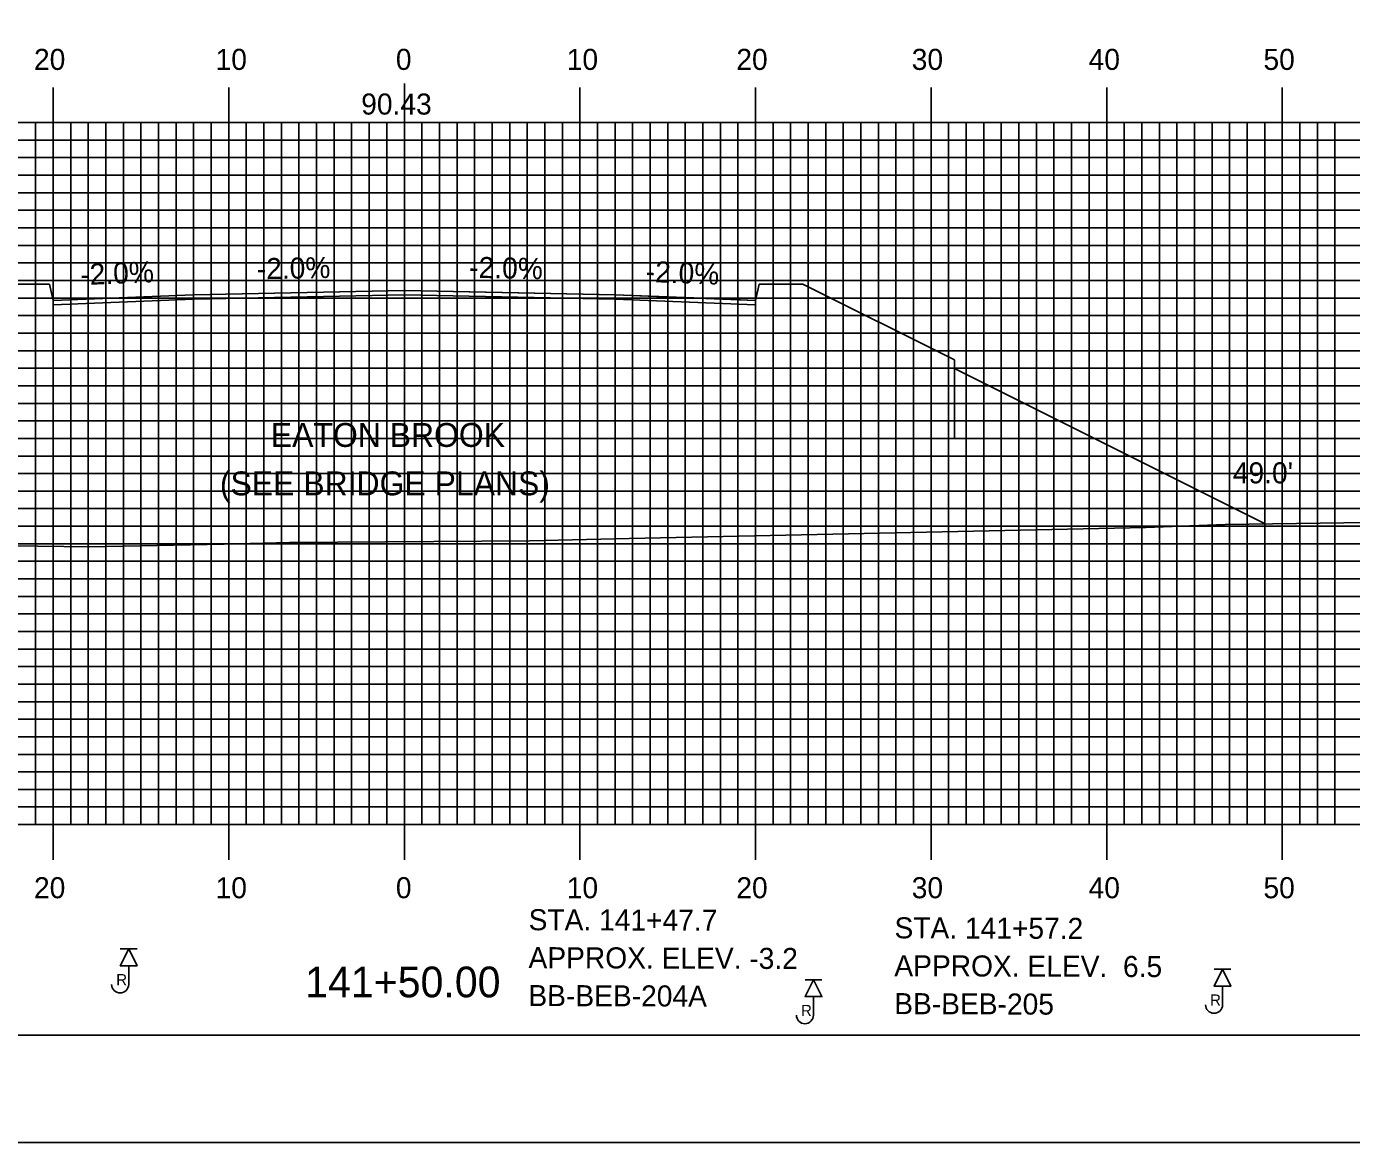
# Model space of a CAD drawing. Extents: x 1776744 to 1777088, y 442591 to 442811.
# Drawn here: x 1776888.7 to 1776964.2, y 442590.5 to 442654.1 of the extents above; entities that cross this region are included whole.
import ezdxf

# ---------------------------------------------------------------- set-up
doc = ezdxf.new("R2010")
doc.units = 0
for name, color, linetype in [('ANNOTATION', 7, 'Continuous'), ('BORDER', 7, 'Continuous'), ('BORING - REFUSAL', 7, 'Continuous'), ('D_Roadway_Centerline', 7, 'Continuous'), ('D_Roadway_Centerline_Text', 7, 'Continuous'), ('D_Roadway_Edge_Shoulder', 7, 'Continuous'), ('D_Roadway_Edge_TW', 7, 'Continuous'), ('D_Roadway_SlopeLines', 7, 'Continuous'), ('D_Text_Standard', 7, 'Continuous'), ('H_V ANNOTATION', 7, 'Continuous'), ('MAJOR', 7, 'Continuous'), ('MINOR', 7, 'Continuous'), ('PLOT BOUNDARY', 7, 'Continuous'), ('S_Roadway_Centerline', 7, 'Continuous')]:
    doc.layers.add(name, color=color, linetype=linetype)

msp = doc.modelspace()

# ---------------------------------------------------------------- linework, layer by layer
at = {"layer": 'BORDER'}
msp.add_lwpolyline([(1776760.651, 442596.665), (1777080.651, 442596.665), (1777080.651, 442806.665), (1776760.651, 442806.665)], close=True, dxfattribs=at)
at = {"layer": 'BORING - REFUSAL'}
for p, q in [((1776895.03, 442601.578), (1776894.071, 442601.578)), ((1776894.551, 442600.618), (1776894.551, 442599.559)), ((1776957.33, 442600.417), (1776956.371, 442600.417)), ((1776934.03, 442599.822), (1776933.071, 442599.822)), ((1776933.551, 442598.862), (1776933.551, 442597.803)), ((1776956.851, 442599.457), (1776956.851, 442598.398))]:
    msp.add_line(p, q, dxfattribs=at)
for points in [[(1776894.551, 442601.578), (1776895.03, 442600.618), (1776894.071, 442600.618)], [(1776956.851, 442600.417), (1776957.33, 442599.457), (1776956.371, 442599.457)], [(1776933.551, 442599.822), (1776934.03, 442598.862), (1776933.071, 442598.862)]]:
    msp.add_lwpolyline(points, close=True, dxfattribs=at)
for centre in [(1776894.066, 442599.559), (1776956.366, 442598.398), (1776933.066, 442597.803)]:
    msp.add_arc(centre, 0.485, 180, 0, dxfattribs=at)
at = {"layer": 'D_Roadway_Centerline'}
msp.add_lwpolyline([(1776890.25, 442638.535), (1776890.253, 442638.535), (1776898.251, 442638.855), (1776898.255, 442638.855), (1776910.251, 442639.095), (1776916.772, 442638.965), (1776922.251, 442638.855), (1776922.256, 442638.855), (1776927.228, 442638.656), (1776930.245, 442638.535), (1776930.25, 442638.535)], dxfattribs=at)
at = {"layer": 'D_Roadway_Edge_Shoulder'}
for points in [[(1776898.251, 442638.855), (1776890.25, 442638.535), (1776890.25, 442638.285), (1776898.251, 442638.605)], [(1776922.251, 442638.855), (1776930.25, 442638.535), (1776930.25, 442638.285), (1776922.251, 442638.605)]]:
    msp.add_lwpolyline(points, close=True, dxfattribs=at)
at = {"layer": 'D_Roadway_Edge_TW'}
msp.add_lwpolyline([(1776898.251, 442638.605), (1776898.251, 442638.855), (1776910.251, 442639.095), (1776922.251, 442638.855), (1776922.251, 442638.605), (1776910.251, 442638.845)], close=True, dxfattribs=at)
at = {"layer": 'D_Roadway_SlopeLines'}
for p, q in [((1776890.047, 442639.465), (1776887.547, 442639.465)), ((1776890.247, 442638.535), (1776890.047, 442639.465)), ((1776930.254, 442638.535), (1776930.454, 442639.465)), ((1776930.454, 442639.465), (1776932.954, 442639.465)), ((1776932.954, 442639.465), (1776941.58, 442635.152)), ((1776941.58, 442635.152), (1776941.58, 442630.64)), ((1776941.58, 442634.652), (1776959.283, 442625.801))]:
    msp.add_line(p, q, dxfattribs=at)
at = {"layer": 'MAJOR'}
for p, q in [((1776890.251, 442650.669), (1776890.251, 442648.665)), ((1776900.251, 442650.669), (1776900.251, 442648.665)), ((1776910.251, 442606.661), (1776910.251, 442650.899)), ((1776910.251, 442650.669), (1776910.251, 442648.665)), ((1776920.251, 442650.669), (1776920.251, 442648.665)), ((1776930.251, 442650.669), (1776930.251, 442648.665)), ((1776940.251, 442650.669), (1776940.251, 442648.665)), ((1776950.251, 442650.669), (1776950.251, 442648.665)), ((1776960.251, 442650.669), (1776960.251, 442648.665)), ((1776770.251, 442648.665), (1777050.251, 442648.665)), ((1776770.251, 442648.665), (1777050.251, 442648.665)), ((1776890.251, 442608.665), (1776890.251, 442648.665)), ((1776900.251, 442608.665), (1776900.251, 442648.665)), ((1776910.251, 442608.665), (1776910.251, 442648.665)), ((1776920.251, 442608.665), (1776920.251, 442648.665)), ((1776930.251, 442608.665), (1776930.251, 442648.665)), ((1776940.251, 442608.665), (1776940.251, 442648.665)), ((1776950.251, 442608.665), (1776950.251, 442648.665)), ((1776960.251, 442608.665), (1776960.251, 442648.665)), ((1776770.251, 442643.665), (1777050.251, 442643.665)), ((1776770.251, 442638.665), (1777050.251, 442638.665)), ((1776770.251, 442633.665), (1777050.251, 442633.665)), ((1776770.251, 442628.665), (1777050.251, 442628.665)), ((1776770.251, 442623.665), (1777050.251, 442623.665)), ((1776770.251, 442618.665), (1777050.251, 442618.665)), ((1776770.251, 442613.665), (1777050.251, 442613.665)), ((1776770.251, 442608.665), (1777050.251, 442608.665)), ((1776770.251, 442608.665), (1777050.251, 442608.665)), ((1776890.251, 442606.661), (1776890.251, 442608.665)), ((1776890.251, 442606.661), (1776890.251, 442608.665)), ((1776900.251, 442606.661), (1776900.251, 442608.665)), ((1776900.251, 442606.661), (1776900.251, 442608.665)), ((1776910.251, 442606.661), (1776910.251, 442608.665)), ((1776920.251, 442606.661), (1776920.251, 442608.665)), ((1776920.251, 442606.661), (1776920.251, 442608.665)), ((1776930.251, 442606.661), (1776930.251, 442608.665)), ((1776930.251, 442606.661), (1776930.251, 442608.665)), ((1776940.251, 442606.661), (1776940.251, 442608.665)), ((1776950.251, 442606.661), (1776950.251, 442608.665)), ((1776960.251, 442606.661), (1776960.251, 442608.665))]:
    msp.add_line(p, q, dxfattribs=at)
at = {"layer": 'MINOR'}
for p, q in [((1776889.251, 442608.665), (1776889.251, 442648.665)), ((1776891.251, 442608.665), (1776891.251, 442648.665)), ((1776892.251, 442608.665), (1776892.251, 442648.665)), ((1776893.251, 442608.665), (1776893.251, 442648.665)), ((1776894.251, 442608.665), (1776894.251, 442648.665)), ((1776895.251, 442608.665), (1776895.251, 442648.665)), ((1776896.251, 442608.665), (1776896.251, 442648.665)), ((1776897.251, 442608.665), (1776897.251, 442648.665)), ((1776898.251, 442608.665), (1776898.251, 442648.665)), ((1776899.251, 442608.665), (1776899.251, 442648.665)), ((1776901.251, 442608.665), (1776901.251, 442648.665)), ((1776902.251, 442608.665), (1776902.251, 442648.665)), ((1776903.251, 442608.665), (1776903.251, 442648.665)), ((1776904.251, 442608.665), (1776904.251, 442648.665)), ((1776905.251, 442608.665), (1776905.251, 442648.665)), ((1776906.251, 442608.665), (1776906.251, 442648.665)), ((1776907.251, 442608.665), (1776907.251, 442648.665)), ((1776908.251, 442608.665), (1776908.251, 442648.665)), ((1776909.251, 442608.665), (1776909.251, 442648.665)), ((1776911.251, 442608.665), (1776911.251, 442648.665)), ((1776912.251, 442608.665), (1776912.251, 442648.665)), ((1776913.251, 442608.665), (1776913.251, 442648.665)), ((1776914.251, 442608.665), (1776914.251, 442648.665)), ((1776915.251, 442608.665), (1776915.251, 442648.665)), ((1776916.251, 442608.665), (1776916.251, 442648.665)), ((1776917.251, 442608.665), (1776917.251, 442648.665)), ((1776918.251, 442608.665), (1776918.251, 442648.665)), ((1776919.251, 442608.665), (1776919.251, 442648.665)), ((1776921.251, 442608.665), (1776921.251, 442648.665)), ((1776922.251, 442608.665), (1776922.251, 442648.665)), ((1776923.251, 442608.665), (1776923.251, 442648.665)), ((1776924.251, 442608.665), (1776924.251, 442648.665)), ((1776925.251, 442608.665), (1776925.251, 442648.665)), ((1776926.251, 442608.665), (1776926.251, 442648.665)), ((1776927.251, 442608.665), (1776927.251, 442648.665)), ((1776928.251, 442608.665), (1776928.251, 442648.665)), ((1776929.251, 442608.665), (1776929.251, 442648.665)), ((1776931.251, 442608.665), (1776931.251, 442648.665)), ((1776932.251, 442608.665), (1776932.251, 442648.665)), ((1776933.251, 442608.665), (1776933.251, 442648.665)), ((1776934.251, 442608.665), (1776934.251, 442648.665)), ((1776935.251, 442608.665), (1776935.251, 442648.665)), ((1776936.251, 442608.665), (1776936.251, 442648.665)), ((1776937.251, 442608.665), (1776937.251, 442648.665)), ((1776938.251, 442608.665), (1776938.251, 442648.665)), ((1776939.251, 442608.665), (1776939.251, 442648.665)), ((1776941.251, 442608.665), (1776941.251, 442648.665)), ((1776942.251, 442608.665), (1776942.251, 442648.665)), ((1776943.251, 442608.665), (1776943.251, 442648.665)), ((1776944.251, 442608.665), (1776944.251, 442648.665)), ((1776945.251, 442608.665), (1776945.251, 442648.665)), ((1776946.251, 442608.665), (1776946.251, 442648.665)), ((1776947.251, 442608.665), (1776947.251, 442648.665)), ((1776948.251, 442608.665), (1776948.251, 442648.665)), ((1776949.251, 442608.665), (1776949.251, 442648.665)), ((1776951.251, 442608.665), (1776951.251, 442648.665)), ((1776952.251, 442608.665), (1776952.251, 442648.665)), ((1776953.251, 442608.665), (1776953.251, 442648.665)), ((1776954.251, 442608.665), (1776954.251, 442648.665)), ((1776955.251, 442608.665), (1776955.251, 442648.665)), ((1776956.251, 442608.665), (1776956.251, 442648.665)), ((1776957.251, 442608.665), (1776957.251, 442648.665)), ((1776958.251, 442608.665), (1776958.251, 442648.665)), ((1776959.251, 442608.665), (1776959.251, 442648.665)), ((1776961.251, 442608.665), (1776961.251, 442648.665)), ((1776962.251, 442608.665), (1776962.251, 442648.665)), ((1776963.251, 442608.665), (1776963.251, 442648.665)), ((1776770.251, 442647.665), (1777050.251, 442647.665)), ((1776770.251, 442646.665), (1777050.251, 442646.665)), ((1776770.251, 442645.665), (1777050.251, 442645.665)), ((1776770.251, 442644.665), (1777050.251, 442644.665)), ((1776770.251, 442642.665), (1777050.251, 442642.665)), ((1776770.251, 442641.665), (1777050.251, 442641.665)), ((1776770.251, 442640.665), (1777050.251, 442640.665)), ((1776770.251, 442639.665), (1777050.251, 442639.665)), ((1776770.251, 442637.665), (1777050.251, 442637.665)), ((1776770.251, 442636.665), (1777050.251, 442636.665)), ((1776770.251, 442635.665), (1777050.251, 442635.665)), ((1776770.251, 442634.665), (1777050.251, 442634.665)), ((1776770.251, 442632.665), (1777050.251, 442632.665)), ((1776770.251, 442631.665), (1777050.251, 442631.665)), ((1776770.251, 442630.665), (1777050.251, 442630.665)), ((1776770.251, 442629.665), (1777050.251, 442629.665)), ((1776770.251, 442627.665), (1777050.251, 442627.665)), ((1776770.251, 442626.665), (1777050.251, 442626.665)), ((1776770.251, 442625.665), (1777050.251, 442625.665)), ((1776770.251, 442624.665), (1777050.251, 442624.665)), ((1776770.251, 442622.665), (1777050.251, 442622.665)), ((1776770.251, 442621.665), (1777050.251, 442621.665)), ((1776770.251, 442620.665), (1777050.251, 442620.665)), ((1776770.251, 442619.665), (1777050.251, 442619.665)), ((1776770.251, 442617.665), (1777050.251, 442617.665)), ((1776770.251, 442616.665), (1777050.251, 442616.665)), ((1776770.251, 442615.665), (1777050.251, 442615.665)), ((1776770.251, 442614.665), (1777050.251, 442614.665)), ((1776770.251, 442612.665), (1777050.251, 442612.665)), ((1776770.251, 442611.665), (1777050.251, 442611.665)), ((1776770.251, 442610.665), (1777050.251, 442610.665)), ((1776770.251, 442609.665), (1777050.251, 442609.665))]:
    msp.add_line(p, q, dxfattribs=at)
at = {"layer": 'PLOT BOUNDARY'}
msp.add_lwpolyline([(1776744.464, 442590.547), (1777084.464, 442590.547), (1777084.464, 442810.547), (1776744.464, 442810.547)], close=True, dxfattribs=at)
at = {"layer": 'S_Roadway_Centerline'}
msp.add_lwpolyline([(1776834.242, 442624.129), (1776857.608, 442624.438), (1776860.996, 442624.48), (1776872.3, 442624.938), (1776880.554, 442624.632), (1776892.317, 442624.488), (1776899.985, 442624.646), (1776903.704, 442624.734), (1776917.397, 442624.822), (1776923.057, 442624.958), (1776952.479, 442625.586), (1776957.006, 442625.77), (1776970.513, 442625.953)], dxfattribs=at)

# ---------------------------------------------------------------- texts
at = {"layer": 'ANNOTATION'}
for rotation, p in [(2.29052, (1776891.819, 442639.4)), (1.14575, (1776901.859, 442639.728)), (358.85424, (1776913.937, 442639.822)), (357.70935, (1776923.978, 442639.588))]:
    msp.add_text('-2.0%', height=1.2, rotation=rotation, dxfattribs=at).set_placement(p)
for s, p in [('EATON BROOK', (1776902.647, 442630.184)), ('(SEE BRIDGE PLANS)', (1776899.746, 442627.424))]:
    msp.add_text(s, height=1.36, dxfattribs=at).set_placement(p)
at = {"layer": 'BORING - REFUSAL'}
for s, p in [('STA. 141+47.7', (1776917.328, 442602.643)), ('STA. 141+57.2', (1776938.165, 442602.182)), ('APPROX. ELEV. -3.2', (1776917.321, 442600.483)), ('APPROX. ELEV.  6.5', (1776938.157, 442600.022)), ('BB-BEB-204A', (1776917.314, 442598.323)), ('BB-BEB-205', (1776938.15, 442597.862))]:
    msp.add_text(s, height=1.2, rotation=359.81416, dxfattribs=at).set_placement(p)
for p in [(1776893.842, 442599.504), (1776956.142, 442598.343), (1776932.842, 442597.747)]:
    msp.add_text('R', height=0.64, dxfattribs=at).set_placement(p)
at = {"layer": 'D_Roadway_Centerline'}
for s, p in [('C', (1776910.246, 442639.095)), ('L', (1776910.251, 442639.088))]:
    msp.add_text(s, height=0.0146, dxfattribs=at).set_placement(p)
at = {"layer": 'D_Roadway_Centerline_Text'}
msp.add_text('90.43', height=1.2, dxfattribs=at).set_placement((1776907.795, 442649.12))
at = {"layer": 'D_Text_Standard'}
msp.add_text("49.0'", height=1.2, dxfattribs=at).set_placement((1776957.436, 442628.105))
at = {"layer": 'H_V ANNOTATION'}
for s, height, p in [('20', 1.2, (1776889.159, 442651.665)), ('10', 1.2, (1776899.501, 442651.665)), ('0', 1.2, (1776909.769, 442651.665)), ('10', 1.2, (1776919.501, 442651.665)), ('20', 1.2, (1776929.159, 442651.665)), ('30', 1.2, (1776939.148, 442651.665)), ('40', 1.2, (1776949.223, 442651.665)), ('50', 1.2, (1776959.18, 442651.665)), ('20', 1.2, (1776889.159, 442604.465)), ('20', 1.2, (1776889.159, 442604.465)), ('10', 1.2, (1776899.501, 442604.465)), ('10', 1.2, (1776899.501, 442604.465)), ('0', 1.2, (1776909.769, 442604.465)), ('0', 1.2, (1776909.769, 442604.465)), ('10', 1.2, (1776919.501, 442604.465)), ('10', 1.2, (1776919.501, 442604.465)), ('20', 1.2, (1776929.159, 442604.465)), ('20', 1.2, (1776929.159, 442604.465)), ('30', 1.2, (1776939.148, 442604.465)), ('40', 1.2, (1776949.223, 442604.465)), ('50', 1.2, (1776959.18, 442604.465)), ('141+50.00', 1.75, (1776904.602, 442598.821))]:
    msp.add_text(s, height=height, dxfattribs=at).set_placement(p)

doc.saveas('drawing.dxf')
